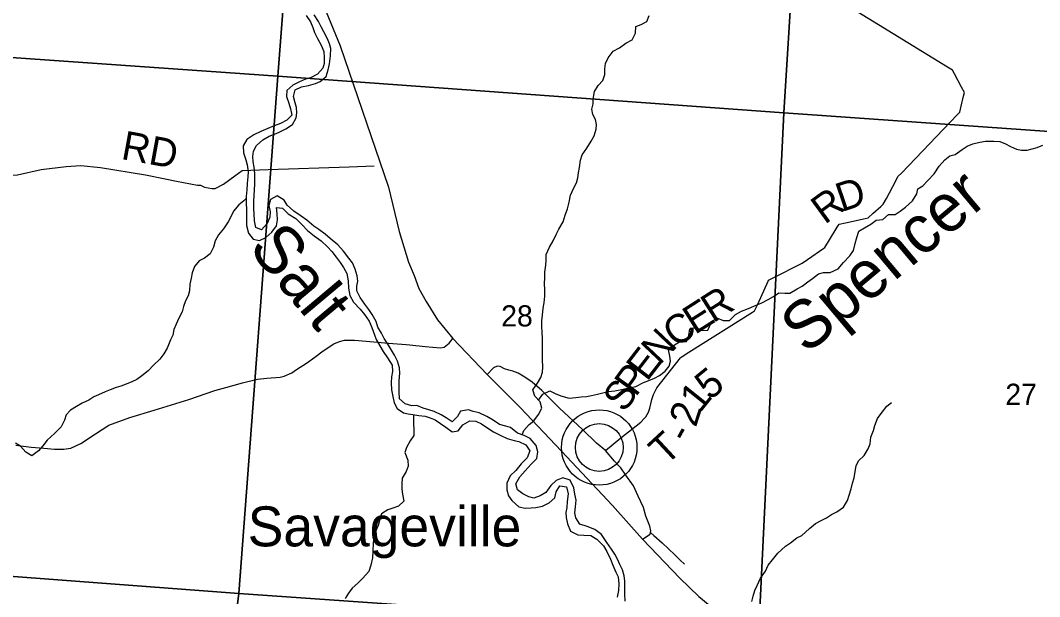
# Model space of a CAD drawing. Extents: x 1715311 to 2083412, y 146837 to 553079.
# Drawn here: x 1900303 to 1910925, y 413322 to 419331 of the extents above; entities that cross this region are included whole.
import ezdxf

# ---------------------------------------------------------------- set-up
doc = ezdxf.new("R2010")
doc.units = 0
for name, color, linetype in [('GM_X_County_Road', 7, 'Continuous'), ('GM_X_Major_River', 7, 'Continuous'), ('GM_X_Major_River_Text', 7, 'Continuous'), ('GM_X_Minor_River', 7, 'Continuous'), ('GM_X_Minor_River_Text', 7, 'Continuous'), ('GM_X_Section', 7, 'Continuous'), ('GM_X_Section_Text', 7, 'Continuous'), ('GM_X_Township_Road', 7, 'Continuous'), ('GM_X_Township_Road_Text', 7, 'Continuous'), ('GM_X_Unincorporated', 7, 'Continuous'), ('GM_X_Unincorporated_Location', 7, 'Continuous'), ('GM_X_Unincorporated_Text', 7, 'Continuous'), ('GM_X_US_Route', 7, 'Continuous')]:
    doc.layers.add(name, color=color, linetype=linetype)

msp = doc.modelspace()

# ---------------------------------------------------------------- linework, layer by layer
at = {"layer": 'GM_X_County_Road'}
for points in [[(1900255, 414900), (1900414, 414882), (1900548, 414870), (1900657, 414858), (1900754, 414858), (1900827, 414870), (1900933, 414918), (1901085, 415018), (1901225, 415111), (1901442, 415189), (1901698, 415268), (1902058, 415377), (1902328, 415470), (1902444, 415504), (1902616, 415550), (1902773, 415590), (1902870, 415601), (1903011, 415610), (1903051, 415621), (1903132, 415657), (1903182, 415691), (1903283, 415758), (1903373, 415819), (1903459, 415884), (1903568, 415959), (1903627, 415984), (1903682, 415995), (1903786, 415995), (1903985, 415980), (1904140, 415964), (1904322, 415950)], [(1904322, 415950), (1904362, 415947), (1904523, 415929), (1904681, 415916), (1904718, 415922), (1904771, 415964), (1904809, 416013)], [(1905490, 415652), (1905435, 415674), (1905392, 415682), (1905348, 415696), (1905304, 415720), (1905273, 415724), (1905232, 415707), (1905168, 415639)], [(1906788, 413920), (1906865, 413974), (1906869, 413992), (1906872, 414007), (1906862, 414056), (1906822, 414161), (1906797, 414250), (1906743, 414371), (1906691, 414476), (1906612, 414590), (1906562, 414664), (1906494, 414734), (1906402, 414846), (1906308, 414923), (1906160, 415065), (1905922, 415287), (1905739, 415471), (1905638, 415559), (1905561, 415610), (1905492, 415651), (1905490, 415652)]]:
    msp.add_lwpolyline(points, dxfattribs=at)
at = {"layer": 'GM_X_Major_River'}
for points in [[(1902726, 417910), (1902731, 417966), (1902765, 418027), (1902830, 418087), (1902896, 418123), (1902950, 418144), (1903001, 418166), (1903071, 418201), (1903140, 418245), (1903176, 418313), (1903183, 418367), (1903179, 418421), (1903167, 418471), (1903148, 418537), (1903166, 418607), (1903233, 418637), (1903305, 418652), (1903377, 418674), (1903427, 418695), (1903490, 418747), (1903510, 418817), (1903525, 418879), (1903535, 418963), (1903540, 419037), (1903524, 419087), (1903505, 419139), (1903467, 419210), (1903439, 419264), (1903410, 419318), (1903366, 419389)], [(1903282, 419381), (1903325, 419315), (1903349, 419257), (1903367, 419206), (1903400, 419142), (1903436, 419074), (1903464, 419005), (1903469, 418945), (1903469, 418883), (1903454, 418831), (1903400, 418770), (1903325, 418732), (1903275, 418717), (1903211, 418689)], [(1903211, 418689), (1903142, 418655), (1903080, 418600), (1903075, 418536), (1903099, 418468), (1903119, 418409), (1903132, 418341), (1903078, 418289), (1903013, 418256), (1902949, 418232), (1902883, 418205), (1902810, 418173), (1902736, 418138), (1902663, 418090), (1902625, 418022), (1902628, 417950), (1902654, 417878), (1902668, 417826), (1902675, 417750), (1902673, 417700), (1902666, 417630), (1902662, 417564), (1902655, 417496), (1902655, 417430), (1902658, 417355), (1902658, 417305), (1902660, 417251), (1902661, 417191), (1902679, 417113), (1902728, 417049), (1902794, 417034), (1902861, 417066), (1902923, 417121), (1902972, 417187), (1902984, 417251), (1902979, 417315), (1902973, 417381), (1903033, 417371), (1903095, 417312), (1903173, 417266), (1903237, 417203), (1903296, 417141), (1903366, 417084), (1903436, 417033), (1903504, 416971), (1903550, 416920), (1903593, 416862), (1903635, 416806), (1903671, 416753), (1903704, 416691), (1903720, 416615), (1903721, 416539), (1903737, 416463), (1903774, 416394), (1903844, 416318), (1903888, 416263), (1903937, 416193), (1903967, 416127), (1903993, 416052), (1904012, 416002), (1904048, 415936), (1904084, 415877), (1904129, 415811), (1904177, 415737), (1904180, 415669), (1904172, 415613), (1904168, 415550), (1904169, 415478), (1904183, 415408), (1904200, 415344), (1904228, 415284), (1904294, 415239), (1904344, 415229), (1904394, 415220), (1904454, 415212), (1904520, 415202), (1904574, 415185), (1904626, 415165), (1904680, 415128), (1904736, 415090), (1904804, 415041), (1904866, 415051), (1904914, 415113), (1904987, 415154), (1905051, 415152), (1905107, 415125), (1905175, 415079), (1905233, 415042), (1905303, 415004), (1905377, 414971), (1905449, 414949), (1905499, 414938), (1905569, 414906), (1905612, 414841), (1905586, 414769), (1905521, 414706), (1905467, 414636), (1905408, 414582), (1905371, 414505), (1905371, 414435), (1905391, 414374)], [(1906091, 414145), (1906083, 414195), (1906089, 414257), (1906094, 414327), (1906080, 414391), (1906071, 414458), (1906033, 414538), (1905955, 414559), (1905887, 414533), (1905832, 414479), (1905780, 414406), (1905721, 414374), (1905653, 414350), (1905601, 414363), (1905541, 414393), (1905485, 414436), (1905466, 414498), (1905508, 414572), (1905565, 414635), (1905627, 414703), (1905686, 414761), (1905696, 414831), (1905679, 414899), (1905617, 414971), (1905553, 415002), (1905483, 415028), (1905411, 415087), (1905361, 415099), (1905297, 415118), (1905230, 415162), (1905164, 415199), (1905084, 415238), (1905022, 415254), (1904972, 415270), (1904891, 415255), (1904859, 415201), (1904804, 415145), (1904739, 415186), (1904687, 415218), (1904615, 415251), (1904561, 415271), (1904499, 415286), (1904433, 415316), (1904383, 415313), (1904314, 415333), (1904255, 415384), (1904249, 415458), (1904252, 415518), (1904252, 415572), (1904257, 415652), (1904253, 415708), (1904233, 415776), (1904202, 415841), (1904172, 415891), (1904140, 415943), (1904095, 416012), (1904065, 416068), (1904027, 416132), (1904010, 416190), (1903970, 416263), (1903934, 416317), (1903893, 416373), (1903845, 416442), (1903809, 416510), (1903810, 416560), (1903818, 416612), (1903812, 416668), (1903793, 416737), (1903763, 416801), (1903727, 416851), (1903670, 416924), (1903610, 416992), (1903532, 417057), (1903479, 417103), (1903413, 417152), (1903361, 417186), (1903287, 417247), (1903229, 417291), (1903153, 417342), (1903084, 417404), (1903052, 417455), (1902978, 417503), (1902910, 417464), (1902893, 417400), (1902905, 417336), (1902902, 417280), (1902874, 417212), (1902815, 417146), (1902757, 417170), (1902744, 417239), (1902738, 417313), (1902737, 417367), (1902735, 417449), (1902740, 417503), (1902744, 417569), (1902746, 417621), (1902747, 417681), (1902745, 417733), (1902740, 417801), (1902730, 417855), (1902726, 417910)], [(1905391, 414374), (1905426, 414324), (1905498, 414257), (1905562, 414243), (1905626, 414247), (1905676, 414250), (1905745, 414264), (1905815, 414299), (1905874, 414351), (1905888, 414413), (1905925, 414477), (1905993, 414466), (1906012, 414394), (1906002, 414314), (1905997, 414250), (1905989, 414198), (1905990, 414146), (1906006, 414082), (1906036, 414005), (1906111, 413967), (1906176, 413962), (1906248, 413960), (1906312, 413921), (1906379, 413853), (1906415, 413792), (1906453, 413712), (1906478, 413650), (1906510, 413577), (1906532, 413527), (1906541, 413455), (1906537, 413385), (1906524, 413317)], [(1906606, 413276), (1906602, 413351), (1906603, 413421), (1906601, 413485), (1906596, 413537), (1906578, 413601), (1906552, 413657), (1906525, 413711), (1906497, 413764), (1906465, 413816), (1906414, 413888), (1906358, 413971), (1906288, 414022), (1906210, 414052), (1906134, 414077), (1906091, 414145)]]:
    msp.add_lwpolyline(points, dxfattribs=at)
at = {"layer": 'GM_X_Minor_River'}
for points in [[(1905531, 415010), (1905549, 415053), (1905604, 415117), (1905654, 415156), (1905704, 415220), (1905736, 415286), (1905719, 415354), (1905665, 415411), (1905643, 415479), (1905691, 415547), (1905728, 415606), (1905744, 415662), (1905748, 415714), (1905744, 415793), (1905743, 415853), (1905743, 415907), (1905743, 416015), (1905741, 416081), (1905736, 416135), (1905738, 416199), (1905744, 416257), (1905752, 416331), (1905761, 416387), (1905769, 416455), (1905767, 416525), (1905765, 416583), (1905768, 416649), (1905770, 416705), (1905780, 416777), (1905782, 416831), (1905784, 416891), (1905817, 416965), (1905855, 417033), (1905887, 417099), (1905916, 417155), (1905960, 417229), (1905982, 417301), (1906004, 417367), (1906021, 417437), (1906035, 417509), (1906071, 417586), (1906098, 417638), (1906114, 417690), (1906120, 417742), (1906130, 417796), (1906142, 417874), (1906159, 417928), (1906207, 417998), (1906251, 418072), (1906283, 418128), (1906304, 418196), (1906308, 418246), (1906296, 418296), (1906268, 418350), (1906258, 418406), (1906271, 418460), (1906273, 418510), (1906285, 418588), (1906323, 418652), (1906372, 418704), (1906394, 418766), (1906394, 418824), (1906400, 418882), (1906427, 418940), (1906481, 419010), (1906547, 419046), (1906613, 419095), (1906678, 419127), (1906712, 419199), (1906716, 419267), (1906772, 419289), (1906830, 419319), (1906855, 419381)], [(1905702, 415372), (1905749, 415432), (1905819, 415468), (1905877, 415440), (1905937, 415416), (1906023, 415393), (1906091, 415399), (1906149, 415407), (1906203, 415408), (1906255, 415418), (1906316, 415434), (1906372, 415446), (1906430, 415460), (1906498, 415469), (1906554, 415477), (1906612, 415491), (1906666, 415501), (1906718, 415512), (1906798, 415554), (1906853, 415574), (1906913, 415600), (1906965, 415628), (1907023, 415673), (1907063, 415725), (1907080, 415777), (1907072, 415829), (1907058, 415897), (1907120, 415949), (1907172, 415979), (1907244, 415983), (1907269, 416045), (1907279, 416113), (1907343, 416128), (1907411, 416096), (1907467, 416100), (1907501, 416176), (1907562, 416230), (1907628, 416201), (1907692, 416201), (1907756, 416263), (1907818, 416297), (1907890, 416328), (1907946, 416352), (1908029, 416384), (1908095, 416420), (1908151, 416451), (1908207, 416491), (1908271, 416487), (1908321, 416485), (1908399, 416530), (1908452, 416558), (1908508, 416604), (1908558, 416640), (1908622, 416688), (1908672, 416703), (1908742, 416703), (1908825, 416741), (1908881, 416805), (1908947, 416874), (1908984, 416932), (1909004, 417006), (1909022, 417066), (1909040, 417134), (1909100, 417168), (1909165, 417206), (1909223, 417246), (1909293, 417253), (1909351, 417305), (1909419, 417307), (1909471, 417343), (1909528, 417382), (1909600, 417450), (1909646, 417522), (1909656, 417574), (1909707, 417604), (1909761, 417662), (1909827, 417732), (1909880, 417811), (1909938, 417877), (1909990, 417917), (1910046, 417933), (1910118, 417985), (1910171, 418020), (1910231, 418044), (1910301, 418062), (1910361, 418070), (1910447, 418073), (1910509, 418067), (1910569, 418045), (1910621, 418015), (1910683, 417988), (1910737, 417978), (1910797, 417978), (1910847, 417992), (1910901, 418007), (1910959, 418029)], [(1902655, 417474), (1902632, 417448), (1902579, 417408), (1902523, 417341), (1902495, 417283), (1902469, 417229), (1902420, 417157), (1902368, 417093), (1902334, 417031), (1902314, 416965), (1902279, 416895), (1902221, 416851), (1902167, 416822), (1902117, 416766), (1902094, 416698), (1902082, 416644), (1902068, 416580), (1902064, 416512), (1902051, 416458), (1902025, 416406), (1902003, 416346), (1901989, 416290), (1901953, 416226), (1901926, 416162), (1901902, 416108), (1901890, 416050), (1901866, 415998), (1901833, 415914), (1901797, 415852), (1901755, 415799), (1901690, 415737), (1901634, 415675), (1901570, 415623), (1901518, 415585), (1901464, 415562), (1901405, 415536), (1901351, 415516), (1901301, 415502), (1901237, 415480), (1901187, 415459), (1901117, 415425), (1901067, 415407), (1901017, 415371), (1900948, 415340), (1900888, 415306), (1900824, 415268), (1900780, 415216), (1900764, 415162), (1900727, 415094), (1900659, 415022), (1900581, 414955), (1900538, 414895), (1900490, 414841), (1900422, 414789), (1900360, 414828), (1900304, 414890), (1900252, 414922)], [(1907925, 413272), (1907941, 413326), (1907957, 413386), (1907980, 413438), (1908016, 413514), (1908068, 413588), (1908097, 413650), (1908141, 413705), (1908197, 413775), (1908277, 413847), (1908328, 413883), (1908396, 413935), (1908448, 413960), (1908526, 414034), (1908591, 414084), (1908649, 414114), (1908703, 414144), (1908755, 414179), (1908811, 414205), (1908882, 414255), (1908924, 414323), (1908942, 414379), (1908962, 414447), (1908975, 414505), (1908991, 414561), (1909003, 414625), (1909015, 414685), (1909037, 414737), (1909096, 414792), (1909138, 414862), (1909160, 414914), (1909166, 414986), (1909193, 415054), (1909209, 415108), (1909235, 415178), (1909275, 415232), (1909332, 415308), (1909382, 415346)], [(1904401, 415219), (1904401, 415198), (1904401, 415121), (1904402, 415067), (1904404, 415001), (1904364, 414946), (1904326, 414878), (1904311, 414824), (1904341, 414745), (1904343, 414681), (1904323, 414625), (1904282, 414556), (1904278, 414498), (1904278, 414442), (1904284, 414389), (1904300, 414319), (1904245, 414264), (1904185, 414246), (1904131, 414226), (1904067, 414184), (1904049, 414130), (1904032, 414062), (1904006, 414008), (1903986, 413938), (1903978, 413882), (1903975, 413794), (1903971, 413728), (1903955, 413650), (1903933, 413584), (1903870, 413510), (1903820, 413463), (1903760, 413409), (1903724, 413357), (1903687, 413303)]]:
    msp.add_lwpolyline(points, dxfattribs=at)
at = {"layer": 'GM_X_Section'}
for points in [[(1898001, 424490), (1903396, 424089), (1902985, 418750), (1897630, 419123)], [(1903396, 424089), (1908594, 423731), (1908259, 418367), (1902985, 418750)], [(1908594, 423731), (1913920, 423360), (1913545, 417994), (1908259, 418367)], [(1897630, 419123), (1902985, 418750), (1902578, 413354), (1897190, 413761)], [(1902985, 418750), (1908259, 418367), (1908000, 412975), (1902578, 413354)], [(1908259, 418367), (1913545, 417994), (1913162, 412614), (1908000, 412975)], [(1897190, 413761), (1902578, 413354), (1901943, 408375), (1896766, 408839)], [(1902578, 413354), (1908000, 412975), (1907500, 407886), (1901943, 408375)]]:
    msp.add_lwpolyline(points, close=True, dxfattribs=at)
at = {"layer": 'GM_X_Township_Road'}
for points in [[(1906402, 414846), (1906561, 414979), (1906769, 415140), (1906804, 415178), (1906821, 415197), (1906849, 415245), (1906863, 415286), (1906884, 415376), (1906902, 415429), (1906937, 415500), (1907183, 415812), (1907189, 415819), (1907270, 415870), (1907933, 416288), (1907955, 416302), (1907988, 416373), (1908097, 416610), (1908101, 416621), (1908184, 416663), (1908417, 416782), (1908449, 416799), (1908505, 416837), (1908678, 416955), (1908687, 416961), (1908736, 417041), (1908817, 417175), (1908835, 417206), (1908902, 417220), (1909106, 417265), (1909137, 417272), (1909191, 417320), (1909269, 417390), (1909295, 417414), (1909328, 417475), (1909426, 417659), (1909449, 417703), (1909488, 417742), (1910066, 418346), (1910094, 418374), (1910108, 418437), (1910132, 418539), (1910142, 418579), (1910111, 418635), (1910037, 418773), (1910016, 418813), (1909965, 418844), (1908987, 419446)], [(1896907, 417239), (1897028, 417232), (1897158, 417232), (1897223, 417222), (1897310, 417232), (1897343, 417232), (1897419, 417243), (1897462, 417284), (1897679, 417580), (1897798, 417688), (1897874, 417753), (1897939, 417797), (1898010, 417794), (1898145, 417753), (1898362, 417742), (1899609, 417710), (1900271, 417720), (1900520, 417775), (1900694, 417796), (1900781, 417807), (1900828, 417811), (1900829, 417811)], [(1900829, 417811), (1900933, 417818), (1901139, 417796), (1901605, 417720), (1901811, 417679)], [(1901811, 417679), (1901812, 417679), (1901930, 417655), (1902147, 417612), (1902180, 417612), (1902223, 417590), (1902299, 417579), (1902332, 417579), (1902418, 417623), (1902538, 417710), (1902614, 417764), (1902885, 417775), (1903729, 417804)], [(1903729, 417804), (1903730, 417804), (1903990, 417813)], [(1906869, 413992), (1906904, 413958), (1906991, 413884), (1907125, 413759), (1907178, 413702), (1907224, 413662)]]:
    msp.add_lwpolyline(points, dxfattribs=at)
at = {"layer": 'GM_X_Unincorporated'}
for radius in [393, 249]:
    msp.add_circle((1906336, 414877), radius, dxfattribs=at)
at = {"layer": 'GM_X_Unincorporated_Location'}
msp.add_line((1906336, 414877), (1906336, 414877), dxfattribs=at)
at = {"layer": 'GM_X_US_Route'}
msp.add_lwpolyline([(1903441, 419539), (1903637, 419064), (1904140, 417593), (1904251, 417128), (1904348, 416809), (1904406, 416672), (1904457, 416536), (1904532, 416399), (1904650, 416210), (1904809, 416013), (1905168, 415639), (1905512, 415295), (1905944, 414839), (1906474, 414273), (1906788, 413920), (1907176, 413513), (1907374, 413324), (1907569, 413164)], dxfattribs=at)

# ---------------------------------------------------------------- texts
at = {"layer": 'GM_X_Major_River_Text'}
msp.add_text('Salt', height=500, rotation=309.9949, dxfattribs=at).set_placement((1902668, 416952))
at = {"layer": 'GM_X_Minor_River_Text'}
msp.add_text('Spencer', height=500, rotation=40.0041, dxfattribs=at).set_placement((1908495, 415839))
at = {"layer": 'GM_X_Section_Text'}
for s, p in [('28', (1905314, 416139)), ('27', (1910568, 415321))]:
    msp.add_text(s, height=221, rotation=0, dxfattribs=at).set_placement(p)
at = {"layer": 'GM_X_Township_Road_Text'}
for s, rotation, p in [('RD', 349.6503, (1901343, 417887)), ('D', 18.7506, (1908864, 417331)), ('R', 36.0104, (1908686, 417197)), ('R', 32.4927, (1907522, 416170)), ('E', 32.5073, (1907333, 416049)), ('C', 34.9805, (1907134, 415910)), ('N', 46.525, (1906964, 415728)), ('E', 52.4392, (1906833, 415557)), ('P', 53.9293, (1906715, 415395)), ('5', 39.3791, (1907489, 415362)), ('S', 54.4369, (1906597, 415231)), ('1', 51.3012, (1907385, 415230)), ('2', 72.1668, (1907342, 415079)), ('T', 42.8782, (1907028, 414680)), ('-', 60.5488, (1907255, 414911))]:
    msp.add_text(s, height=300, rotation=rotation, dxfattribs=at).set_placement(p)
at = {"layer": 'GM_X_Unincorporated_Text'}
msp.add_text('Savageville', height=417, rotation=0, dxfattribs=at).set_placement((1902672, 413846))

doc.saveas('drawing.dxf')
